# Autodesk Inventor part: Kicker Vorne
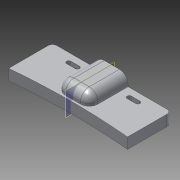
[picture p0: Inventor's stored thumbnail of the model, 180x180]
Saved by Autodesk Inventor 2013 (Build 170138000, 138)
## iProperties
Created: 2012-07
Part Number: Kicker Vorne
Material: Aluminium 6061
Document SubType Name: Modeling
Designer: rYan
Mass: 16.3879 g
Surface Area: 35.9771 cm^2
Volume: 6.04719 cm^3
Density: 2.71 g/cm^3
Author: rYan
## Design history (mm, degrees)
sketch "Skizze1"
  geometry: L1 (-27.5, 0)-(27.5, 0); L2 (27.5, 0)-(27.5, -20.263); L3 (-27.5, 0)-(-27.5, -20.263); L4 (0, 63.8)-(0, -382.8) reference; L5 (-38.5, 0)-(38.5, 0) reference; L6 (27.5, -19)-(-27.5, -19); A1 r 300 centre (0, -319) between (27.5, -20.263) and (-27.5, -20.263); 1 further point
  constraints: 8 end point, 2 perpendicular, 2 point on circle, 2 point on line, 1 centre point, 1 collinear, 1 horizontal, 1 parallel, 1 symmetric about line, 1 tangent, 1 other
  dimensions: "d0" = 55 distance of L1.start L1.end; "d2" = 300 radius of A1; "d3" = 19 distance between parallel lines of L1 L6
extrude "Extrusion1" new body sketch "Skizze1" distance "d4" = 5; taper "d5" = 0 deg
sketch "Skizze2"
  geometry: L1 (27.5, 0)-(-27.5, 0) reference; L2 (0, 4.053)-(0, -24.316) reference; L3 (-7.5, 0)-(7.5, 0); L4 (7.5, 0)-(7.5, -18); L5 (7.5, -18)-(-7.5, -18); L6 (-7.5, -18)-(-7.5, 0); 1 further point
  constraints: 8 end point, 2 parallel, 1 horizontal, 1 perpendicular, 1 point on line, 1 other
  dimensions: "d6" = 15 distance of L4.end L5.end; "d8" = 18 distance of L5.end L3.start
extrude "Extrusion2" join sketch "Skizze2" distance "d9" = 5; taper "d10" = 0 deg
sketch "Skizze3"
  geometry: L1 (35, -10)-(20, -10) reference; L2 (27.5, 0)-(27.5, -10); L3 (55, 0)-(55, -5) reference; L4 (0, 0)-(0, -5) reference; L5 (55, -5)-(0, -5); L6 (0, 0)-(55, 0) reference; 1 further point
  constraints: 4 end point, 2 midpoint, 2 point on line, 1 perpendicular
  dimensions: "d11" = 5 distance between parallel lines of L6 L5
hole "Bohrung1" sketch "Skizze3" at (27.5, -5) diameter "d12" = 6.647; stored, may be unused: countersink angle "d16" = 90 deg, drill point angle "d18" = 118 deg; dims "d13" = 11, "d14" = 9, "d15" = 2, "d17" = 14
sketch "Skizze5"
  geometry: L1 (7.5, -18)-(-7.5, -18) reference; L2 (27.5, 0)-(7.5, 0) reference; L3 (12, -3)-(16, -3); L4 (12, -5)-(16, -5); L5 (11, -3.001)-(11, -5.001); L6 (0, -18)-(0, 0); A1 r 1 centre (12, -4) between (12, -3) and (12, -5); A2 r 1 centre (16, -4) between (16, -5) and (16, -3)
  constraints: 8 end point, 5 tangent, 4 point on circle, 3 parallel, 2 centre point, 1 midpoint, 1 perpendicular
  dimensions: "d23" = 4 distance of A2.centre A1.centre; "d25" = 2 distance between parallel lines of L4 L3; "d26" = 11 distance between parallel lines of L6 L5; "d27" = 3 distance between parallel lines of L2 L3
extrude "Extrusion4" cut sketch "Skizze5" stored distance "d28" = 10; taper "d29" = 0 deg
workplane "Arbeitsebene2"
mirror "Spiegeln2"
fillet "Rundung1" dims "d30" = 4
fillet "Fillet2" dims "d34" = 2
node "Volumenkörper1"
